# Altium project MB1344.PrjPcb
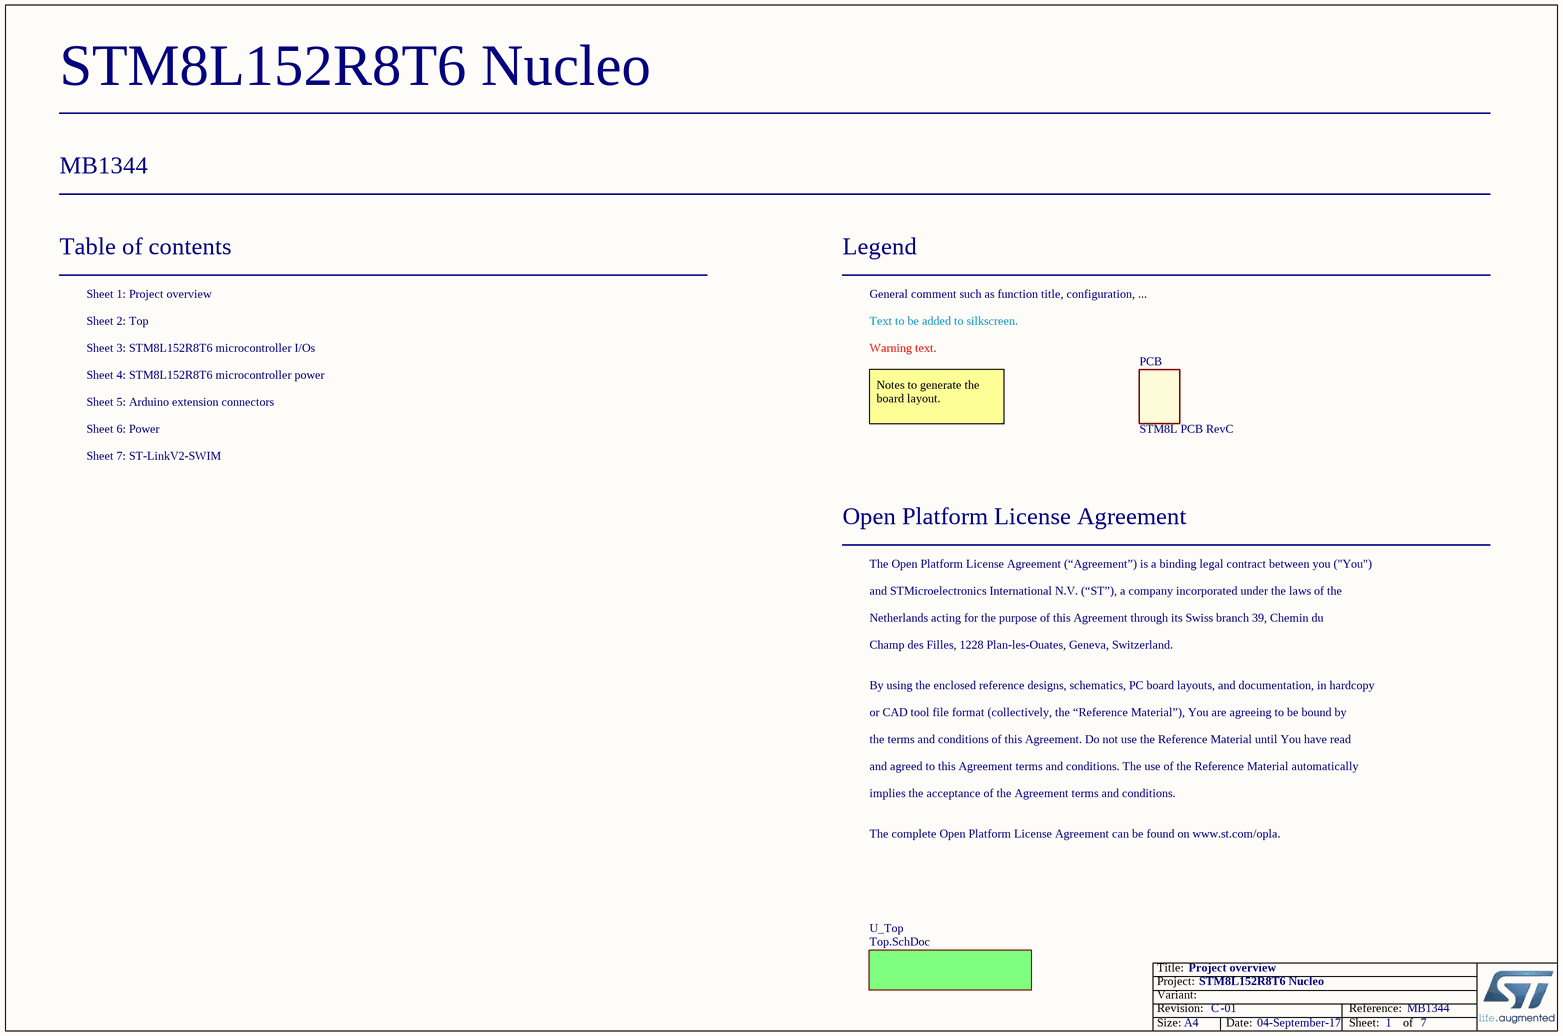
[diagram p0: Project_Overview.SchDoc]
Board_Reference: MB1344; Board_PCB_Revision: C; Board_Name: STM8L152R8T6 Nucleo; Board_Document_Date: 04-September-17; Board_Assembly_Revision: 01
7 sheets, 133 parts. Net scope: flat (ports and power ports of the same name join across sheets).
Board file: MB1344.PcbDoc
Sheets:
  Project_Overview.SchDoc
    U_Top = Top.SchDoc
      U_Power = Power.SchDoc
      U_ST-LinkV2_SWIM = ST-LinkV2_SWIM.SchDoc
      U_Arduino_extension_connectors = Arduino_extension_connectors.SchDoc
      U_STM8L152R8T6 microcontroller IOs = STM8L152R8T6 microcontroller IOs.SchDoc
      U_STM8L152R8T6 microcontroller power = STM8L152R8T6 microcontroller power.SchDoc

## Sheet Project_Overview.SchDoc: Project overview
size A4; ApprovedBy: Not used; CheckedBy: Not used; Author: Not used; CompanyName: STMicroelectronics; DrawnBy: Not used; Engineer: Not used; Organization: Not used; Address1: Not used; Address2: Not used; Address3: Not used; Address4: Not used; DocumentNumber: MB1134; Revision: Not used; SheetNumber: 1; SheetTotal: 7

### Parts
PCB  value STM8L PCB RevC  (hidden comment: PCB)

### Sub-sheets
U_Top = Top.SchDoc: no entries

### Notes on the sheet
- Table of contents
- Sheet 1: Project overview
- Legend
- General comment such as function title, configuration, ...
- Sheet 2: Top
- Sheet 3: STM8L152R8T6 microcontroller I/Os
- Sheet 4: STM8L152R8T6 microcontroller power
- Text to be added to silkscreen.
- Warning text.
- Sheet 6: Power
- Sheet 5: Arduino extension connectors
- Notes to generate the board layout.
- Sheet 7: ST-LinkV2-SWIM
- Open Platform License Agreement
- The Open Platform License Agreement (“Agreement”) is a binding legal contract between you ("You")
- and STMicroelectronics International N.V. (“ST”), a company incorporated under the laws of the
- Netherlands acting for the purpose of this Agreement through its Swiss branch 39, Chemin du
- Champ des Filles, 1228 Plan-les-Ouates, Geneva, Switzerland.
- By using the enclosed reference designs, schematics, PC board layouts, and documentation, in hardcopy
- or CAD tool file format (collectively, the “Reference Material”), You are agreeing to be bound by
- the terms and conditions of this Agreement. Do not use the Reference Material until You have read
- and agreed to this Agreement terms and conditions. The use of the Reference Material automatically
- implies the acceptance of the Agreement terms and conditions.
- The complete Open Platform License Agreement can be found on www.st.com/opla.

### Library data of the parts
PCB = 1001001000655: 2-LAYE PCB,White Soldermask,Blue ink PANTONE 2955 Silkscreen,lead Gold,70mm*82.5mm,STM8L PCB RevC; Manufacturer: XJX

## Sheet Top.SchDoc: Top
size A4; Date: Not used; ApprovedBy: Not used; CheckedBy: Not used; Author: Not used; CompanyName: STMicroelectronics; DrawnBy: Not used; Engineer: Not used; Organization: Not used; Address1: Not used; Address2: Not used; Address3: Not used; Address4: Not used; DocumentNumber: MB1134; Revision: Not used; SheetNumber: 2; SheetTotal: 7
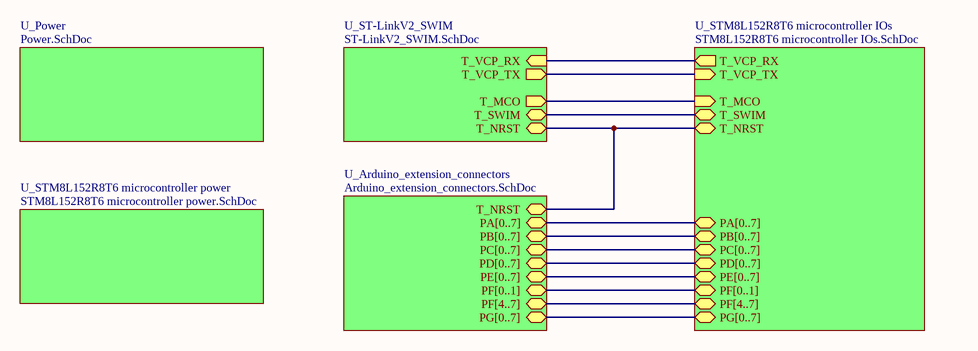
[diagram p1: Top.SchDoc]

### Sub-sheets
U_Arduino_extension_connectors = Arduino_extension_connectors.SchDoc: PA[0..7] (bidir), PB[0..7] (bidir), PC[0..7] (bidir), PD[0..7] (bidir), PE[0..7] (bidir), PF[0..1] (bidir), PF[4..7] (bidir), PG[0..7] (bidir), T_NRST (bidir)
U_Power = Power.SchDoc: no entries
U_ST-LinkV2_SWIM = ST-LinkV2_SWIM.SchDoc: T_VCP_RX (in), T_VCP_TX (out), T_MCO (out), T_NRST (bidir), T_SWIM (bidir)
U_STM8L152R8T6 microcontroller IOs = STM8L152R8T6 microcontroller IOs.SchDoc: T_VCP_TX (in), T_VCP_RX (out), T_NRST (bidir), T_SWIM (bidir), T_MCO (in), PA[0..7] (bidir), PB[0..7] (bidir), PC[0..7] (bidir), PD[0..7] (bidir), PE[0..7] (bidir), PF[0..1] (bidir), PF[4..7] (bidir), PG[0..7] (bidir)
U_STM8L152R8T6 microcontroller power = STM8L152R8T6 microcontroller power.SchDoc: no entries

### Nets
(unnamed): sheet U_ST-LinkV2_SWIM/T_VCP_RX, sheet U_STM8L152R8T6 microcontroller IOs/T_VCP_RX
(unnamed): sheet U_ST-LinkV2_SWIM/T_VCP_TX, sheet U_STM8L152R8T6 microcontroller IOs/T_VCP_TX  [a separate net that carries the same name]
(unnamed): sheet U_ST-LinkV2_SWIM/T_MCO, sheet U_STM8L152R8T6 microcontroller IOs/T_MCO  [a separate net that carries the same name]
(unnamed): sheet U_ST-LinkV2_SWIM/T_NRST, sheet U_Arduino_extension_connectors/T_NRST, sheet U_STM8L152R8T6 microcontroller IOs/T_NRST  [a separate net that carries the same name]
(unnamed): sheet U_ST-LinkV2_SWIM/T_SWIM, sheet U_STM8L152R8T6 microcontroller IOs/T_SWIM  [a separate net that carries the same name]

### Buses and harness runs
bus sheet U_Arduino_extension_connectors/PA[0..7] = sheet U_STM8L152R8T6 microcontroller IOs/PA[0..7]
bus sheet U_Arduino_extension_connectors/PB[0..7] = sheet U_STM8L152R8T6 microcontroller IOs/PB[0..7]
bus sheet U_Arduino_extension_connectors/PC[0..7] = sheet U_STM8L152R8T6 microcontroller IOs/PC[0..7]
bus sheet U_Arduino_extension_connectors/PD[0..7] = sheet U_STM8L152R8T6 microcontroller IOs/PD[0..7]
bus sheet U_Arduino_extension_connectors/PE[0..7] = sheet U_STM8L152R8T6 microcontroller IOs/PE[0..7]
bus sheet U_Arduino_extension_connectors/PF[0..1] = sheet U_STM8L152R8T6 microcontroller IOs/PF[0..1]
bus sheet U_Arduino_extension_connectors/PF[4..7] = sheet U_STM8L152R8T6 microcontroller IOs/PF[4..7]
bus sheet U_Arduino_extension_connectors/PG[0..7] = sheet U_STM8L152R8T6 microcontroller IOs/PG[0..7]

## Sheet Power.SchDoc: Power
size A4; Date: Not used; ApprovedBy: Not used; CheckedBy: Not used; Author: Not used; CompanyName: STMicroelectronics; DrawnBy: Not used; Engineer: Not used; Organization: Not used; Address1: Not used; Address2: Not used; Address3: Not used; Address4: Not used; DocumentNumber: MB1134; Revision: Not used; SheetNumber: 6; SheetTotal: 7
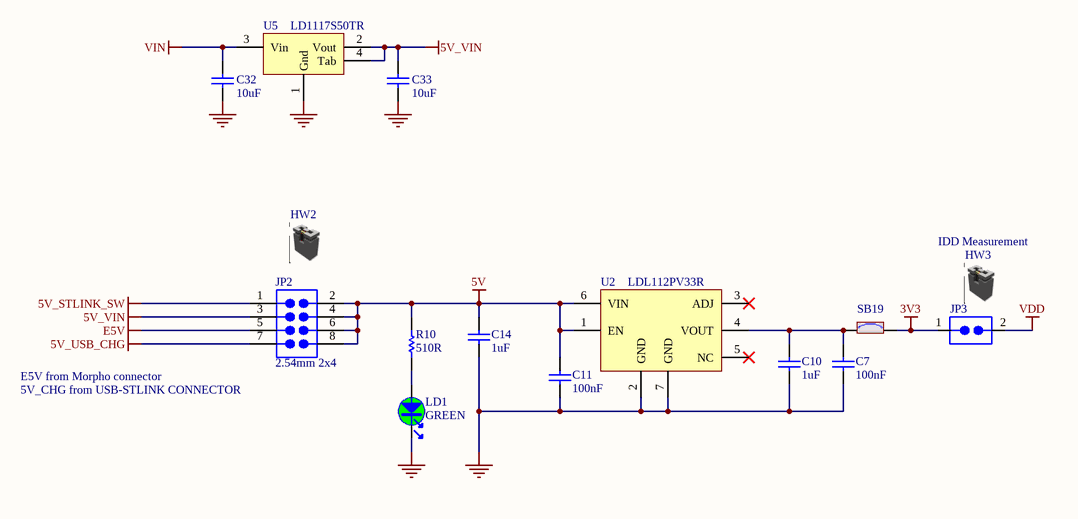
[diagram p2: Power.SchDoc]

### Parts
C7  value 100nF  [C0603]  (hidden comment: C)
C10  value 1uF  [C0603]  (hidden comment: C)
C11  value 100nF  [C0603]  (hidden comment: C)
C14  value 1uF  [C0603]  (hidden comment: C)
C32  value 10uF  [C0805]  (hidden comment: C)
C33  value 10uF  [C0805]  (hidden comment: C)
HW2  Shunt  (value not drawn)  (mechanical)
HW3  Shunt  (value not drawn)  (mechanical)
JP2  value 2.54mm 2x4  [HDRVS8W64P254_2X4_1016X750X850P]  (hidden comment: HEAD2X4)
JP3  SIP2  [HDRV2W64P254_1X2_508X254X854P]  (value not drawn)
LD1  value GREEN  [D0603]  (hidden comment: LED_green)
R10  value 510R  [R0603]  (hidden comment: R)
SB19  SB_ON  [JP2_SMD]  (value not drawn)
U2  LDL112PV33R  [DFN300X300X80-7N]
U5  LD1117S50TR  [SOT-223]

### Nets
3V3: JP3.1 SB19.2
5V: C11.2 C14.2 JP2.2 JP2.4 JP2.6 JP2.8 R10.2 U2.1(EN) U2.6(VIN)
5V_STLINK_SW: JP2.1
5V_USB_CHG: JP2.7
5V_VIN: C33.2 JP2.3 U5.2(Vout) U5.4(Tab)
E5V: JP2.5
GND: C7.1 C10.1 C11.1 C14.1 C32.1 C33.1 LD1.1 U2.2(GND) U2.7(GND) U5.1(Gnd)
VDD: JP3.2
VIN: C32.2 U5.3(Vin)
NetC7_2: C7.2 C10.2 SB19.1 U2.4(VOUT)
NetLD1_2: LD1.2 R10.1

Not connected (* = marked no-connect by the designer): U2 3(ADJ)* 5(NC)*

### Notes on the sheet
- (near HW3) IDD Measurement
- E5V from Morpho connector
- 5V_CHG from USB-STLINK CONNECTOR

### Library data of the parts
C7 C11 = 1004001100110: CAP,100NF,+/-10%,X7R,50V,SMD0603; Manufacturer: MURATA; Manufacturer_Part_Number: GRM188R71H104KA93D
C10 C14 = 1004001100120: CAP,1UF,+/-10%,X7R,16V,SMD0603; Manufacturer: MURATA; Manufacturer_Part_Number: GRM188R71C105KA12D
C32 C33 = 1004001100159: CAP,10UF,+/-10%,X5R,16V,SMD0805; Manufacturer: MURATA; Manufacturer_Part_Number: GRM21BR61C106KE15L
HW2 = 1009016000005: Connector,Shunt,open type 2Pin,2.54MM Pitch,6MM Height,Gold Flash 1u,black,Bulk; Manufacturer: TOWNES; Manufacturer_Part_Number: MJ501-EOGF-B-K
HW3 = 1009016000005: Connector,Shunt,open type 2Pin,2.54MM Pitch,6MM Height,Gold Flash 1u,black,Bulk; Manufacturer_Part_Number: MJ501-EOGF-B-K; Manufacturer: TOWNES
JP2 = 1009001100223: Connector,Pin Header,Straight,Male,2x4Pin,2.54MM pitch,6.0mm,Gold Flash  Over NI,black,SMD; Manufacturer: MTCONN; Manufacturer_Part_Number: PD254NV-08GC310
JP3 = 1009001200085R1: Connector,Pin Header,Straight,Male,1x2Pin,2.54MM pitch,6.0,3.0,Au over 50 u nickle , black,DIP; Manufacturer: MTCONN; Manufacturer_Part_Number: JT254-D180-102-001; Value: 2.54mm 1x2
LD1 = 1006001100094: LED,Yellow-Green,Water clear,20mA,0603,573nm,Vf:2.0v;; Manufacturer: EVERLIGHT; Manufacturer_Part_Number: 19-213SYGC/S530-E2/TR8
R10 = 1003001100424: RES,510R,+/-5%,1/10W,SMD0603; Manufacturer: YAGEO; Manufacturer_Part_Number: RC0603JR-07510RL
SB19 = PN029: RES,0R,+/-5%,1/10W,SMD0603; Manufacturer: YAGEO; Manufacturer_Part_Number: RC0603JR-070RL
U2 = 1002006100237C: IC,LDO,1.2 A low quiescent current LDO with reverse current protection 3.3V,LDL112PV33R,DFN3x3,SMD; Manufacturer: ST
U5 = 1002006100169C: IC,LDO,5V,LD1117S50TR,SOT223,STMicroelectronics,9176133; Manufacturer: ST

## Sheet ST-LinkV2_SWIM.SchDoc: ST-Link/V2 SWIM mode
size A4; Date: Not used; ApprovedBy: Not used; CheckedBy: Not used; Author: Not used; CompanyName: STMicroelectronics; DrawnBy: Not used; Engineer: Not used; Organization: Not used; Address1: Not used; Address2: Not used; Address3: Not used; Address4: Not used; DocumentNumber: MB1134; Revision: Not used; SheetNumber: 7; SheetTotal: 7
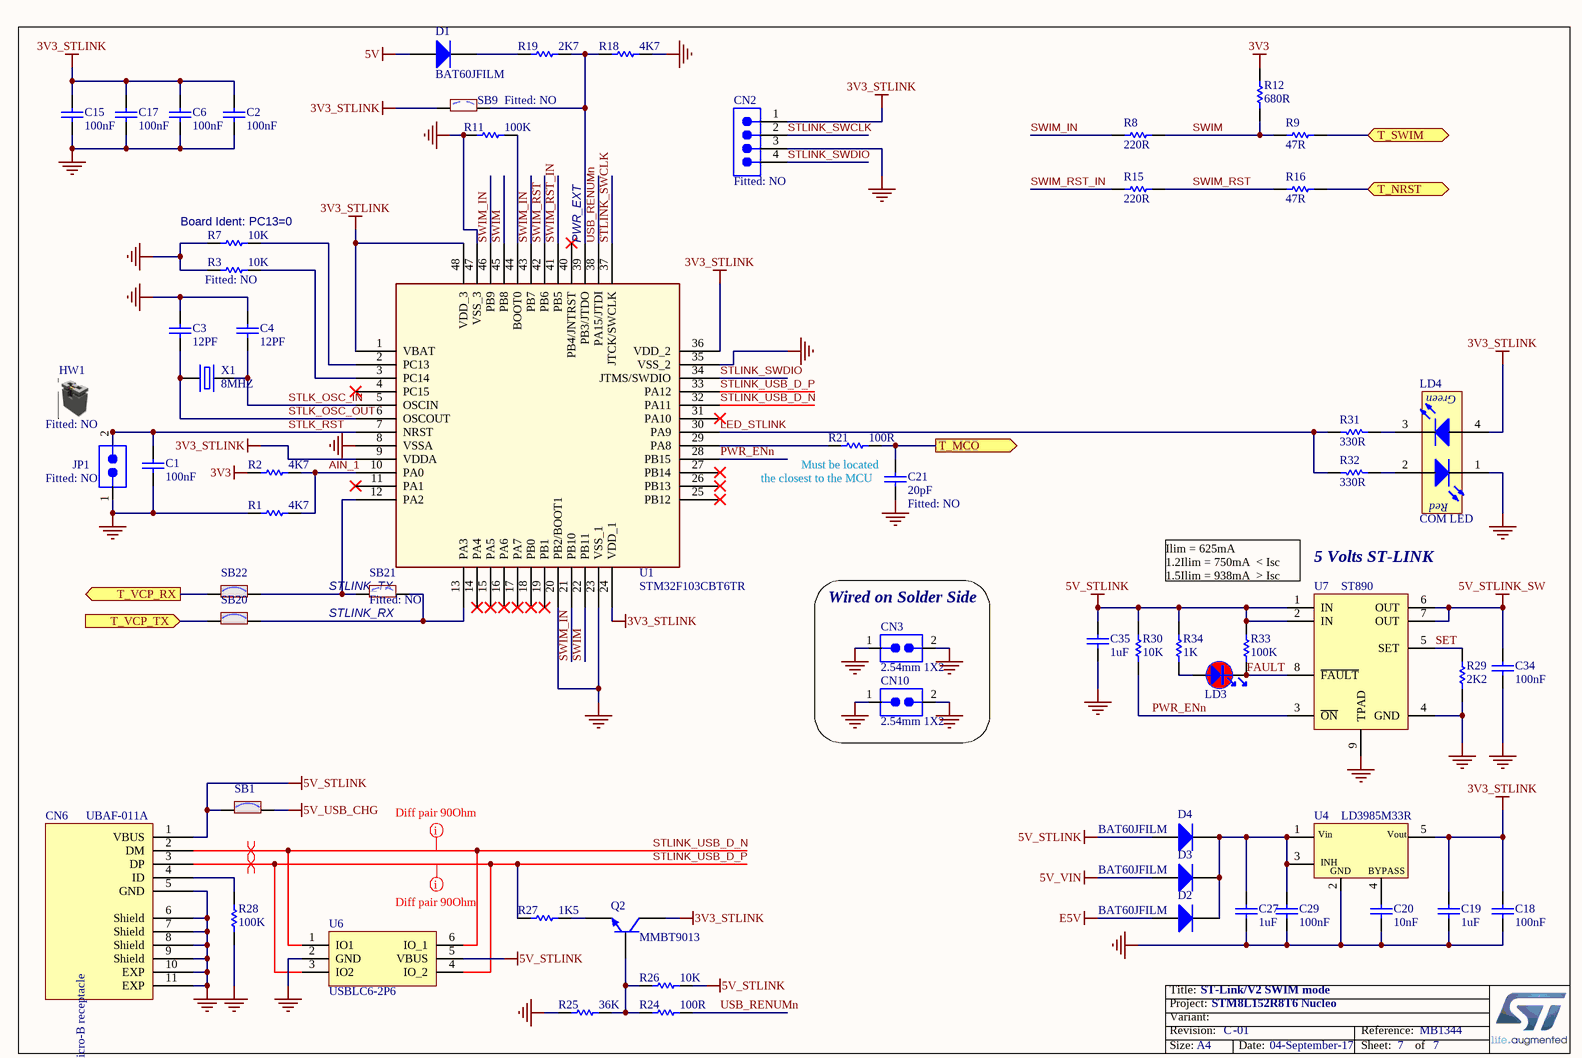
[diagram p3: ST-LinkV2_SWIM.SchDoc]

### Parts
C1  value 100nF  [C0603]  (hidden comment: C)
C2  value 100nF  [C0603]  (hidden comment: C)
C3  value 12PF  [C0603]  (hidden comment: C)
C4  value 12PF  [C0603]  (hidden comment: C)
C6  value 100nF  [C0603]  (hidden comment: C)
C15  value 100nF  [C0603]  (hidden comment: C)
C17  value 100nF  [C0603]  (hidden comment: C)
C18  value 100nF  [C0603]  (hidden comment: C)
C19  value 1uF  [C0603]  (hidden comment: C)
C20  value 10nF  [C0603]  (hidden comment: C)
C21  value 20pF  Fitted: NO  [C0603]  (hidden comment: C)
C27  value 1uF  [C0603]  (hidden comment: C)
C29  value 100nF  [C0603]  (hidden comment: C)
C34  value 100nF  [C0603]  (hidden comment: C)
C35  value 1uF  [C0603]  (hidden comment: C)
CN2  Fitted: NO  [HDRV4W64P254_1X4_1016X254X854P]  (hidden comment: SIP4)
CN3  value 2.54mm 1X2  [HDRV2W64P254_1X2_508X250X854P]  (hidden comment: SIP2)
CN6  value UBAF-011A  [USB-MICRO-B-5P-SMD_800X560]  (hidden comment: MICROUSB5_6)
CN10  value 2.54mm 1X2  [HDRV2W64P254_1X2_508X250X854P]  (hidden comment: SIP2)
D1  value BAT60JFILM  [SOD323]  (hidden comment: D)
D2  value BAT60JFILM  [SOD323]  (hidden comment: D)
D3  value BAT60JFILM  [SOD323]  (hidden comment: D)
D4  value BAT60JFILM  [SOD323]  (hidden comment: D)
HW1  Fitted: NO  (hidden comment: Shunt)  (mechanical)
JP1  Fitted: NO  [HDRV2W64P254_1X2_508X254X854P]  (hidden comment: SIP2)
LD3  LED_red  [D0603]  (value not drawn)
LD4  value COM LED  [PLCC150P350X280X210-4N]  (hidden comment: LED4_RED/GRN)
Q2  value MMBT9013  [TO-236]  (hidden comment: NPN)
R1  value 4K7  [R0603]  (hidden comment: R)
R2  value 4K7  [R0603]  (hidden comment: R)
R3  value 10K  Fitted: NO  [R0603]  (hidden comment: R)
R7  value 10K  [R0603]  (hidden comment: R)
R8  value 220R  [R0603]  (hidden comment: R)
R9  value 47R  [R0603]  (hidden comment: R)
R11  value 100K  [R0603]  (hidden comment: R)
R12  value 680R  [R0603]  (hidden comment: R)
R15  value 220R  [R0603]  (hidden comment: R)
R16  value 47R  [R0603]  (hidden comment: R)
R18  value 4K7  [R0603]  (hidden comment: R)
R19  value 2K7  [R0603]  (hidden comment: R)
R21  value 100R  [R0603]  (hidden comment: R)
R24  value 100R  [R0603]  (hidden comment: R)
R25  value 36K  [R0603]  (hidden comment: R)
R26  value 10K  [R0603]  (hidden comment: R)
R27  value 1K5  [R0603]  (hidden comment: R)
R28  value 100K  [R0603]  (hidden comment: R)
R29  value 2K2  [R0603]  (hidden comment: R)
R30  value 10K  [R0603]  (hidden comment: R)
R31  value 330R  [R0603]  (hidden comment: R)
R32  value 330R  [R0603]  (hidden comment: R)
R33  value 100K  [R0603]  (hidden comment: R)
R34  value 1K  [R0603]  (hidden comment: R)
SB1  SB_ON  [JP2_SMD]  (value not drawn)
SB9  Fitted: NO  [JP2_SMD]  (hidden comment: SB_OFF)
SB20  SB_ON  [JP2_SMD]  (value not drawn)
SB21  Fitted: NO  [JP2_SMD]  (hidden comment: SB_OFF)
SB22  SB_ON  [JP2_SMD]  (value not drawn)
U1  value STM32F103CBT6TR  [QFP50P900X900X160-48N]  (hidden comment: STM32F103CBT6)
U4  LD3985M33R  [SOT23-5]
U6  USBLC6-2P6  [SOT-666]
U7  ST890  [SOIC127P600X175-8N+PQFN65P300X300X90_HS-9N]
X1  value 8MHZ  [XTAL320X250X100N]  (hidden comment: X)

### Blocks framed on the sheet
Wired on Solder Side: CN3 CN10

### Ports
T_MCO (out), T_NRST (bidir), T_SWIM (bidir), T_VCP_RX (out), T_VCP_TX (in)

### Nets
3V3: R2.1 R12.2
3V3_STLINK: C2.2 C6.2 C15.2 C17.2 C18.2 C19.2 CN2.1 LD4.4(YellowGreen_anode) Q2.3(C) SB9.1 U1.1(VBAT) U1.9(VDDA) U1.24(VDD_1) U1.36(VDD_2) U1.48(VDD_3) U4.5(Vout)
5V: D1.2
5V_STLINK: C35.1 CN6.1(VBUS) D4.2 R26.1 R30.1 R33.2 R34.2 SB1.1 U6.5(VBUS) U7.1(IN) U7.2(IN)
5V_STLINK_SW: C34.2 U7.6(OUT) U7.7(OUT)
5V_USB_CHG: SB1.2
5V_VIN: D3.2
E5V: D2.2
GND: C1.1 C2.1 C3.2 C4.2 C6.1 C15.1 C17.1 C18.1 C19.1 C20.1 C21.1 C27.1 C29.1 C34.1 C35.2 CN2.3 CN3.1 CN3.2 CN6.5(GND) CN6.6(Shield) CN6.7(Shield) CN6.8(Shield) CN6.9(Shield) CN6.10(EXP) CN6.11(EXP) CN10.1 CN10.2 JP1.1 LD4.1(RED_cathode) R1.1 R3.1 R7.1 R11.1 R18.2 R25.1 R28.1 R29.1 U1.8(VSSA) U1.20(PB2/BOOT1) U1.23(VSS_1) U1.35(VSS_2) U1.47(VSS_3) U4.2(GND) U6.2(GND) U7.4(GND) U7.9(TPAD)
AIN_1: R1.2 R2.2 U1.10(PA0)
FAULT: LD3.1 R33.1 U7.8(~{FAULT})
LED_STLINK: R31.2 R32.2 U1.30(PA9)
PWR_ENn: R30.2 U1.28(PB15) U7.3(~{ON})
SET: R29.2 U7.5(SET)
STLINK_SWCLK: CN2.2 U1.37(JTCK/SWCLK)
STLINK_SWDIO: CN2.4 U1.34(JTMS/SWDIO)
STLINK_USB_D_N: CN6.2(DM) U1.32(PA11) U6.1(IO1) U6.6(IO_1)
STLINK_USB_D_P: CN6.3(DP) R27.2 U1.33(PA12) U6.3(IO2) U6.4(IO_2)
STLK_OSC_IN: C4.1 U1.5(OSCIN) X1.2
STLK_OSC_OUT: C3.1 U1.6(OSCOUT) X1.1
STLK_RST: C1.2 JP1.2 U1.7(NRST)
SWIM: R8.1 R9.2 R12.1 U1.22(PB11) U1.45(PB8)
SWIM_IN: R8.2 U1.21(PB10) U1.43(PB7) U1.46(PB9)
SWIM_RST: R15.1 R16.2 U1.42(PB6)
SWIM_RST_IN: R15.2 U1.41(PB5)
T_MCO: C21.2 R21.2 ; port T_MCO
T_NRST: R16.1 ; port T_NRST
T_SWIM: R9.1 ; port T_SWIM
T_VCP_RX: SB22.1 ; port T_VCP_RX
T_VCP_TX: SB20.1 ; port T_VCP_TX
USB_RENUMn: R24.2 U1.38(PA15/JTDI)
NetC20_2: C20.2 U4.4(BYPASS)
NetC27_2: C27.2 C29.2 D2.1 D3.1 D4.1 U4.1(Vin) U4.3(CE)
NetCN6_4: CN6.4(ID) R28.2
NetD1_1: D1.1 R19.1
NetLD3_2: LD3.2 R34.1
NetLD4_2: LD4.2(Red_anode) R32.1
NetLD4_3: LD4.3(YellowGreen_cathode) R31.1
NetQ2_1: Q2.1(B) R24.1 R25.2 R26.2
NetQ2_2: Q2.2(E) R27.1
NetR3_2: R3.2 U1.3(PC14)
NetR7_2: R7.2 U1.2(PC13)
NetR11_2: R11.2 U1.44(BOOT0)
NetR18_1: R18.1 R19.2 SB9.2 U1.39(PB3/JTDO)
NetR21_1: R21.1 U1.29(PA8)
NetSB20_2: SB20.2 SB21.2 U1.13(PA3)
NetSB21_1: SB21.1 SB22.2 U1.12(PA2)

Not connected (* = marked no-connect by the designer): U1 4(PC15)* 11(PA1)* 14(PA4)* 15(PA5)* 16(PA6)* 17(PA7)* 18(PB0)* 19(PB1)* 25(PB12)* 26(PB13)* 27(PB14)* 31(PA10)* 40(PB4/JNTRST)*

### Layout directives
mark named Diff pair 90Ohm: STLINK_USB_D_N, STLINK_USB_D_P
differential pair: STLINK_USB_D_N, STLINK_USB_D_P

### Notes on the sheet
- (near R7) Board Ident: PC13=0
- (near U1) PWR_EXT
- (near C21) Must be located
- (near C21) the closest to the MCU
- STLINK_TX
- (near U7) Ilim = 625mA
  1.2Ilim = 750mA  < Isc
  1.5Ilim = 938mA  > Isc
- (near U7) 5 Volts ST-LINK
- STLINK_RX

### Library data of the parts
C1 C2 C6 C15 C17 C18 C29 C34 = 1004001100110: as C7 on sheet Power
C3 C4 = 1004001100897: CAP,12PF,+/-5%,NPO,50V,SMD0603; Manufacturer: Yageo; Manufacturer_Part_Number: CC0603JRNPO9BN120
C19 C27 C35 = 1004001100120: as C10 on sheet Power
C20 = 1004001100103: CAP,10NF,+/-10%,X7R,50V,SMD0603; Manufacturer: MURATA; Manufacturer_Part_Number: GRM188R71H103KA01D
C21 = 1004001100069: CAP,20PF,+/-5%,C0G,50V,SMD0603; Manufacturer: MURATA; Manufacturer_Part_Number: GRM1885C1H200JA01D
CN2 = 1009001200307: Connector,Pin Header,Straight,Male,1x4Pin,2.54MM pitch,6.0,3.0,Au over 50 u nickle , black,DIP; Manufacturer: MTCONN; Manufacturer_Part_Number: JT254-D180-104-001; Value: 2.54mm 1x4
CN3 CN10 = 1009001200378: Connector,Pin Header,Straight,Male,2.54MM pitch,1x2P,6.0mm,10mm,Au Over 50u"NI, black,DIP; Manufacturer: MTCONN; Manufacturer_Part_Number: JTP254-D180-102-185L
CN6 = 1009007100040R2: Connector,MicroUSB B port,5 Position,Right Angle,Gold Flash 1u, black,SMD; Manufacturer: MTCONN
D1-D4 = 1006002100076C: DIODE SCHOTTKY,BAT60JFILM,10V,3A, SOD323/A,ST,(X3 Code 9151097)
HW1 = 1009016000005: as HW2 on sheet Power
JP1 = 1009001200085R1: as JP3 on sheet Power
LD3 = 1006001100139: LED,Briliant Red,WATER CLEAR,0603 TR; Manufacturer: EVERLIGHT; Value: 19-213/R6C-AP1Q2B/3T
LD4 = 1006001100098: LED IND RED/GRN TOP MOUNT 4PLCC,3.2*2.8MM; Manufacturer: AVAGO; Manufacturer_Part_Number: HSMF-A201-A00J1
Q2 = 1006013100039: Trans,NPN,MMBT9013G-I-AE3-R,Ic:500mA,Vceo:20v, SOT-23,SMD; Manufacturer: UTC
R1 R2 R18 = 1003001100221: RES,4K7,+/-5%,1/10W,SMD0603; Manufacturer: YAGEO; Manufacturer_Part_Number: RC0603JR-074K7L
R3 R7 R26 R30 = 1003001100235: RES,10K,+/-5%,1/10W,SMD0603; Manufacturer: YAGEO; Manufacturer_Part_Number: RC0603JR-0710KL
R8 R15 = 1003001100192: RES,220R,+/-5%,1/10W,SMD0603; Manufacturer: YAGEO; Manufacturer_Part_Number: RC0603JR-07220RL
R9 R16 = 1003001100178: RES,47R,+/-5%,1/10W,SMD0603; Manufacturer: YAGEO; Manufacturer_Part_Number: RC0603JR-0747RL
R11 R28 R33 = 1003001100269: RES,100K,+/-5%,1/10W,SMD0603; Manufacturer: YAGEO; Manufacturer_Part_Number: RC0603JR-07100KL
R12 = 1003001100200: RES,680R,+/-5%,1/10W,SMD0603; Manufacturer: YAGEO; Manufacturer_Part_Number: RC0603JR-07680RL
R19 = 1003001100467: RES,2K7,+/-1%,1/10W,SMD0603; Manufacturer: YAGEO; Manufacturer_Part_Number: RC0603FR-072K7L
R21 R24 = 1003001100186: RES,100R,+/-5%,1/10W,SMD0603; Manufacturer: YAGEO; Manufacturer_Part_Number: RC0603JR-07100RL
R25 = 1003001100368: RES,36K, +/-1%,1/10W,SMD0603; Manufacturer: YAGEO; Manufacturer_Part_Number: RC0603FR-0736KL
R27 = 1003001100207: RES,1K5,+/-5%,1/10W,SMD0603; Manufacturer: YAGEO; Manufacturer_Part_Number: RC0603JR-071K5L
R29 = 1003001100211: RES,2K2,+/-1%,1/10W,SMD0603; Manufacturer: YAGEO; Manufacturer_Part_Number: RC0603FR-072K2L
R31 R32 = 1003001100196: RES,330R,+/-5%,1/10W,SMD0603; Manufacturer: YAGEO; Manufacturer_Part_Number: RC0603JR-07330RL
R34 = 1003001100202: RES,1K,+/-5%,1/10W,SMD0603; Manufacturer: YAGEO; Manufacturer_Part_Number: RC0603JR-071KL
SB1 SB20 SB22 = PN029: as SB19 on sheet Power
SB9 SB21 = PN034: RES,0R,+/-5%,1/10W,SMD0603; Manufacturer: YAGEO; Manufacturer_Part_Number: RC0603JR-070RL
U1 = 1002001100035C: IC, ARM Cortex-M3 MCU,STM32F103CBT6,LQFP-48,SMD,TR,(9175111),customer supply; Manufacturer: ST
U4 = 1002006100166C: IC,LDO,3.3V,LD3985M33R,SOT23-5L,ST,(X3 Code 9176161)
U6 = 1002020100274C: IC,ESD Protection for High Speed Interface Protection 2.5 PF Low Cap,USBLC6-2P6, SOT-666,SMD,TR; Manufacturer: ST
U7 = 1002004100103C: IC PWR SWITCH,ST890CDR,SO-8,ST,(X3 Code 9172002)
X1 = 1008002100145C: CRYSTAL, 8pF, -+50PPM,NX3225GD-8MHz-EXS00A-CG04874,SMT; Manufacturer: NDK

## Sheet Arduino_extension_connectors.SchDoc: Arduino extension connectors
size A4; Date: Not used; ApprovedBy: Not used; CheckedBy: Not used; Author: Not used; CompanyName: STMicroelectronics; DrawnBy: Not used; Engineer: Not used; Organization: Not used; Address1: Not used; Address2: Not used; Address3: Not used; Address4: Not used; DocumentNumber: MB1134; Revision: Not used; SheetNumber: 5; SheetTotal: 7
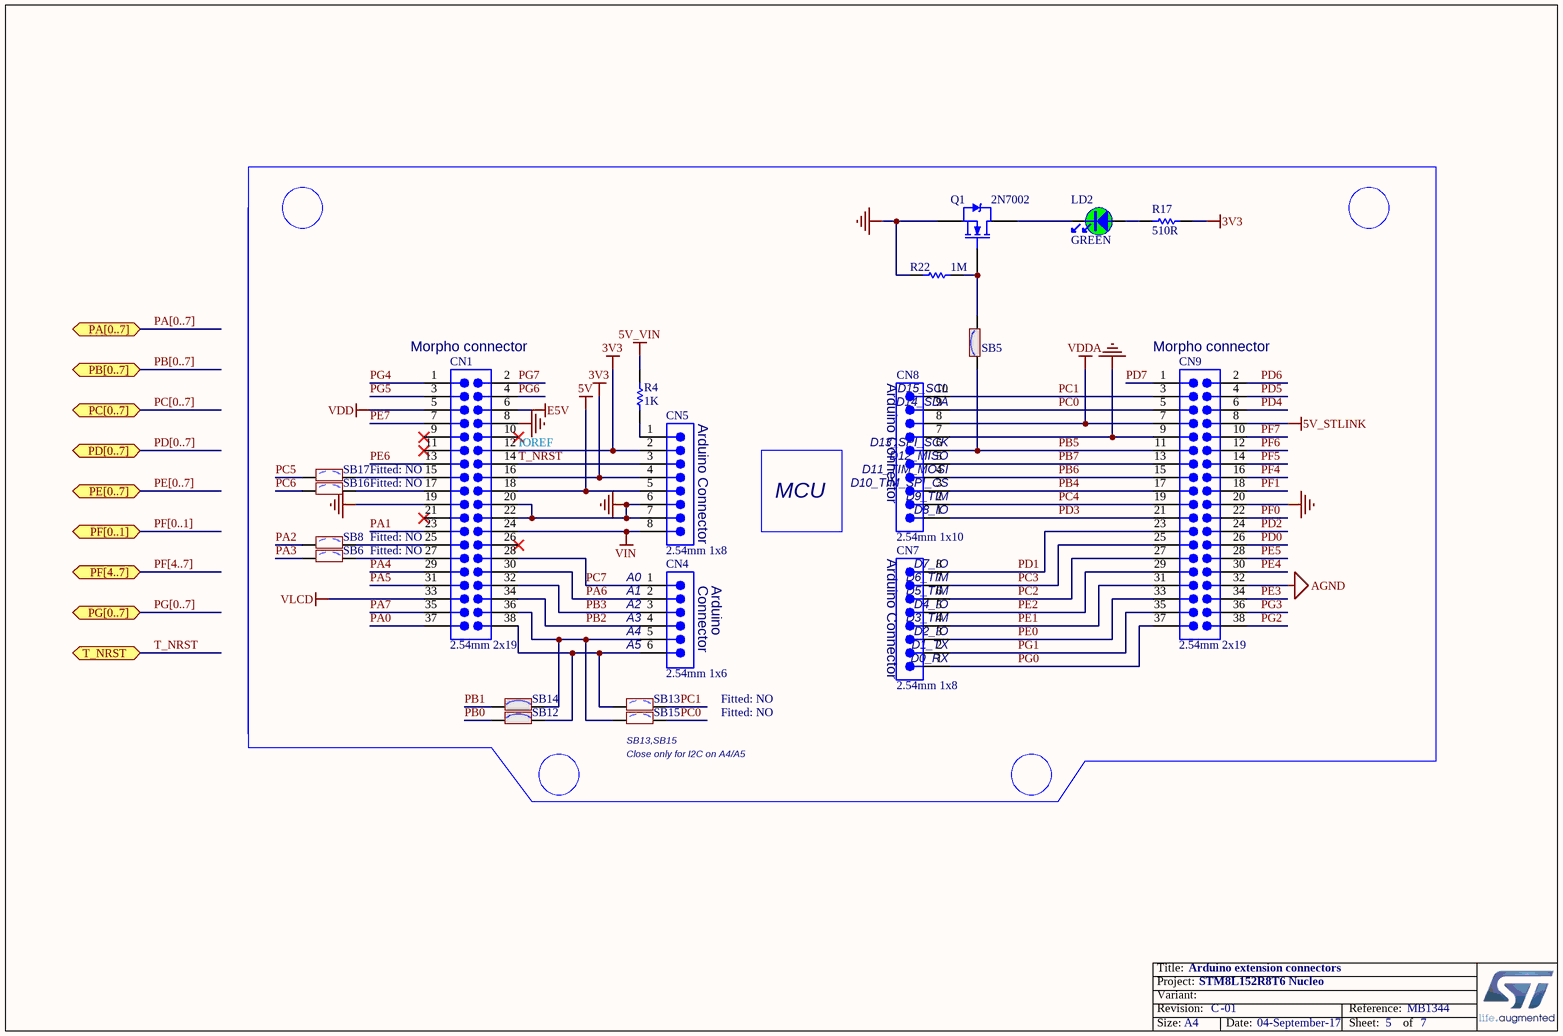
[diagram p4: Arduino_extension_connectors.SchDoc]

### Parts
CN1  value 2.54mm 2x19  [HDRV38W64P254_2X19_4826X508X838P]  (hidden comment: HEAD2X19)
CN4  value 2.54mm 1x6  [SOKV2W64P254_1X6_1574X250X850P]  (hidden comment: SIP6)
CN5  value 2.54mm 1x8  [SOKV2W64P254_1X8_2082X250X850P]  (hidden comment: SIP8)
CN7  value 2.54mm 1x8  [SOKV2W64P254_1X8_2082X250X850P]  (hidden comment: SIP8)
CN8  value 2.54mm 1x10  [SOKV2W64P254_1X10_2590X250X850P]  (hidden comment: SIP10)
CN9  value 2.54mm 2x19  [HDRV38W64P254_2X19_4826X508X838P]  (hidden comment: HEAD2X19)
LD2  value GREEN  [D0603]  (hidden comment: LED_green)
Q1  value 2N7002  [TO-236]  (hidden comment: NMOS)
R4  value 1K  [R0603]  (hidden comment: R)
R17  value 510R  [R0603]  (hidden comment: R)
R22  value 1M  [R0603]  (hidden comment: R)
SB5  SB_ON  [JP2_SMD]  (value not drawn)
SB6  Fitted: NO  [JP2_SMD]  (hidden comment: SB_OFF)
SB8  Fitted: NO  [JP2_SMD]  (hidden comment: SB_OFF)
SB12  SB_ON  [JP2_SMD]  (value not drawn)
SB13  Fitted: NO  [JP2_SMD]  (hidden comment: SB_OFF)
SB14  SB_ON  [JP2_SMD]  (value not drawn)
SB15  Fitted: NO  [JP2_SMD]  (hidden comment: SB_OFF)
SB16  Fitted: NO  [JP2_SMD]  (hidden comment: SB_OFF)
SB17  Fitted: NO  [JP2_SMD]  (hidden comment: SB_OFF)

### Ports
PA[0..7] (bidir), PB[0..7] (bidir), PC[0..7] (bidir), PD[0..7] (bidir), PE[0..7] (bidir), PF[0..1] (bidir), PF[4..7] (bidir), PG[0..7] (bidir), T_NRST

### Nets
3V3: CN1.12 CN1.16 CN5.2 CN5.4 R17.1
5V: CN1.18 CN5.5
5V_STLINK: CN9.8
5V_VIN: R4.2
AGND: CN9.32
E5V: CN1.6
GND: CN1.8 CN1.19 CN1.20 CN1.22 CN5.6 CN5.7 CN8.7 CN9.9 CN9.20 Q1.2(S) R22.1
VDD: CN1.5
VDDA: CN8.8 CN9.7
VIN: CN1.24 CN5.8
VLCD: CN1.33
PA0: CN1.37
PA1: CN1.23
PA2: SB8.1
PA3: SB6.1
PA4: CN1.29
PA5: CN1.31
PA6: CN1.30 CN4.2
PA7: CN1.35
PB0: SB12.1
PB1: SB14.1
PB2: CN1.34 CN4.4
PB3: CN1.32 CN4.3
PB4: CN8.3 CN9.17
PB5: CN8.6 CN9.11 SB5.1
PB6: CN8.4 CN9.15
PB7: CN8.5 CN9.13
PC0: CN8.9 CN9.5 SB15.2
PC1: CN8.10 CN9.3 SB13.2
PC2: CN7.6 CN9.27
PC3: CN7.7 CN9.25
PC4: CN8.2 CN9.19
PC5: SB17.1
PC6: SB16.1
PC7: CN1.28 CN4.1
PD0: CN9.26
PD1: CN7.8 CN9.23
PD2: CN9.24
PD3: CN8.1 CN9.21
PD4: CN9.6
PD5: CN9.4
PD6: CN9.2
PD7: CN9.1
PE0: CN7.3 CN9.33
PE1: CN7.4 CN9.31
PE2: CN7.5 CN9.29
PE3: CN9.34
PE4: CN9.30
PE5: CN9.28
PE6: CN1.13
PE7: CN1.7
PF0: CN9.22
PF1: CN9.18
PF4: CN9.16
PF5: CN9.14
PF6: CN9.12
PF7: CN9.10
PG0: CN7.1 CN9.37
PG1: CN7.2 CN9.35
PG2: CN9.38
PG3: CN9.36
PG4: CN1.1
PG5: CN1.3
PG6: CN1.4
PG7: CN1.2
T_NRST: CN1.14 CN5.3 ; port T_NRST
NetCN1_15: CN1.15 SB17.2
NetCN1_17: CN1.17 SB16.2
NetCN1_25: CN1.25 SB8.2
NetCN1_27: CN1.27 SB6.2
NetCN1_36: CN1.36 CN4.5 SB14.2 SB15.1
NetCN1_38: CN1.38 CN4.6 SB12.2 SB13.1
NetCN5_1: CN5.1 R4.1
NetLD2_1: LD2.1 Q1.3(D)
NetLD2_2: LD2.2 R17.2
NetQ1_1: Q1.1(G) R22.2 SB5.2

Not connected (* = marked no-connect by the designer): CN1 9* 10* 11* 21* 26*

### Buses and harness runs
bus PA[0..7] = port PA[0..7]
bus PB[0..7] = port PB[0..7]
bus PC[0..7] = port PC[0..7]
bus PD[0..7] = port PD[0..7]
bus PE[0..7] = port PE[0..7]
bus PF[0..1] = port PF[0..1]
bus PF[4..7] = port PF[4..7]
bus PG[0..7] = port PG[0..7]

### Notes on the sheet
- (near CN1) Morpho connector
- (near CN8) Arduino Connector
- (near CN9) Morpho connector
- (near CN1) IOREF
- (near CN5) Arduino Connector
- D14_SDA
- D15_SCL
- (near CN8) D13_SPI_SCK
- MCU
- (near CN8) D8_IO
- (near CN8) D9_TIM
- (near CN8) D10_TIM_SPI_CS
- (near CN8) D12_MISO
- (near CN8) D11_TIM_MOSI
- (near CN4) A0
- (near CN4) Connector
- (near CN4) Arduino
- (near CN7) Arduino Connector
- (near CN7) D6_TIM
- (near CN7) D7_IO
- (near CN4) A1
- (near CN4) A2
- (near CN4) A3
- (near CN4) A4
- (near CN4) A5
- (near CN7) D1_TX
- (near CN7) D2_IO
- (near CN7) D4_IO
- (near CN7) D3_TIM
- (near CN7) D5_TIM
- (near CN7) D0_RX
- Close only for I2C on A4/A5
- (near SB15) SB13,SB15

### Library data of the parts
CN1 CN9 = 1009001200377: Connector,Pin Header,Straight,Male,2.54MM pitch,2x19P,6.0mm,10mm,Au Over 50u"NI, black,DIP; Manufacturer: MTCONN; Manufacturer_Part_Number: JTP254-D180-219-06L
CN4 = 1009002200189: Connector,Pin Socket,Straight,Female,1x6Pin,2.54MM pitch,8.5,9.92,Gold Flash 1u, black,DIP; Manufacturer: MTCONN; Manufacturer_Part_Number: JT254F-D180-850-106-10DO-G
CN5 CN7 = 1009002200162: Connector,Pin Socket,Straight,Female,1x8Pin,2.54MM pitch,8.5,9.92,Gold Flash 1u, black,DIP; Manufacturer: MTCONN; Manufacturer_Part_Number: JT254F-D180-850-108-10DO-G
CN8 = 1009002200163: Connector,Pin Socket,Straight,Female,1x10Pin,2.54MM pitch,8.5,9.92,Gold Flash 1u, black,DIP; Manufacturer: MTCONN; Manufacturer_Part_Number: JT254F-D180-850-110-10DO-G
LD2 = 1006001100094: as LD1 on sheet Power
Q1 = 1006015100003: Mosfet,N-Channel,2N7002,60V,115mA,SOT-23,SMD; Manufacturer: FAIRCHILD
R4 = 1003001100202: as R34 on sheet ST-LinkV2_SWIM
R17 = 1003001100424: as R10 on sheet Power
R22 = 1003001100291: RES,1M,+/-5%,1/10W,SMD0603; Manufacturer: YAGEO; Manufacturer_Part_Number: RC0603JR-071ML
SB5 SB12 SB14 = PN029: as SB19 on sheet Power
SB6 SB8 SB13 SB15-SB17 = PN034: as SB9 on sheet ST-LinkV2_SWIM

## Sheet STM8L152R8T6 microcontroller IOs.SchDoc: STM32 microcontroller I/Os
size A4; DocumentNumber: MB1134; Revision: C.3; SheetNumber: 3; SheetTotal: 7; Project: NUCLEO-XXXXRX
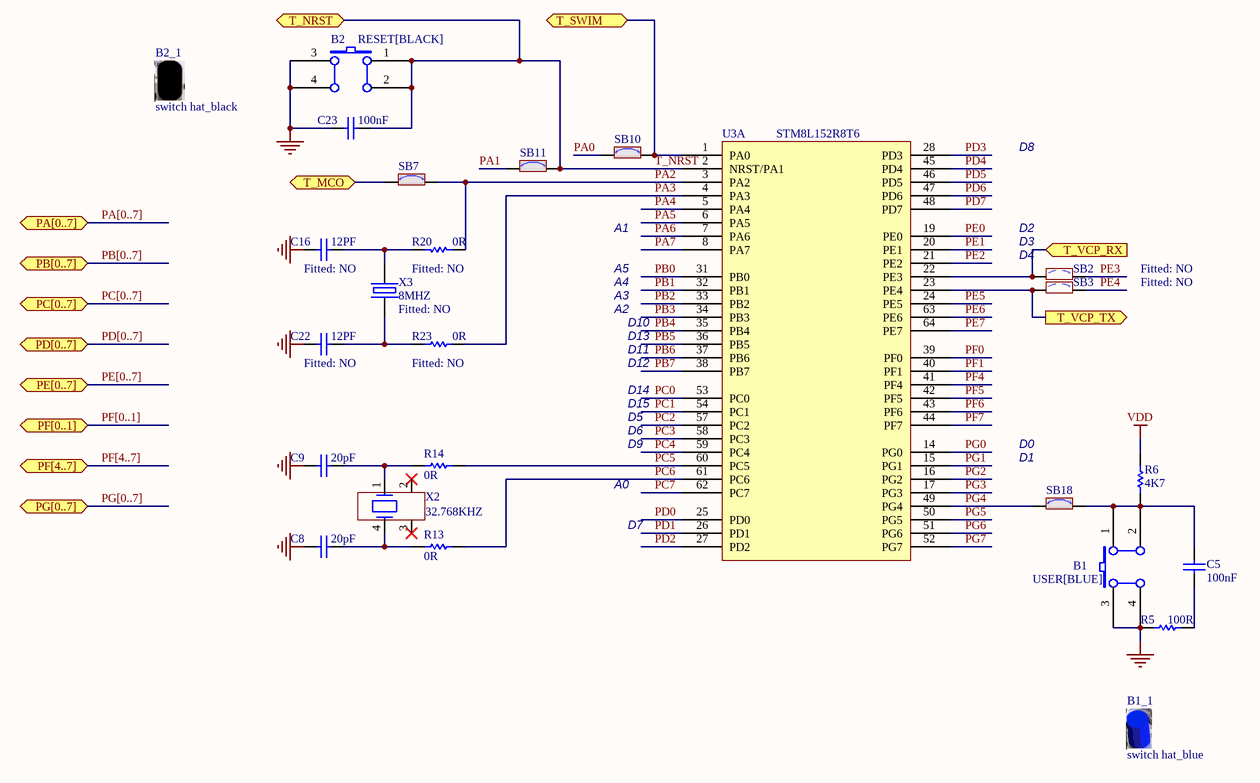
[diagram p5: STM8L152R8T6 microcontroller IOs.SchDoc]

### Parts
B1  value USER[BLUE]  [SW4P600X600]  (hidden comment: SW PUSHBUTTON)
B1_1  switch hat_blue  (mechanical)
B2  value RESET[BLACK]  [SW4P600X600]  (hidden comment: SW PUSHBUTTON)
B2_1  switch hat_black  (mechanical)
C5  value 100nF  [C0603]  (hidden comment: C)
C8  value 20pF  [C0603]  (hidden comment: C)
C9  value 20pF  [C0603]  (hidden comment: C)
C16  value 12PF  Fitted: NO  [C0603]  (hidden comment: C)
C22  value 12PF  Fitted: NO  [C0603]  (hidden comment: C)
C23  value 100nF  [C0603]  (hidden comment: C)
R5  value 100R  [R0603]  (hidden comment: R)
R6  value 4K7  [R0603]  (hidden comment: R)
R13  value 0R  [R0603]  (hidden comment: R)
R14  value 0R  [R0603]  (hidden comment: R)
R20  value 0R  Fitted: NO  [R0603]  (hidden comment: R)
R23  value 0R  Fitted: NO  [R0603]  (hidden comment: R)
SB2  Fitted: NO  [JP2_SMD]  (hidden comment: SB_OFF)
SB3  Fitted: NO  [JP2_SMD]  (hidden comment: SB_OFF)
SB7  SB_ON  [JP2_SMD]  (value not drawn)
SB10  SB_ON  [JP2_SMD]  (value not drawn)
SB11  SB_ON  [JP2_SMD]  (value not drawn)
SB18  SB_ON  [JP2_SMD]  (value not drawn)
U3  STM8L152R8T6  [QFP50P1000X1000X160-64N]  (part A of 2)
X2  value 32.768KHZ  [OSCCC380X800X250-4N]  (hidden comment: MC306)
X3  value 8MHZ  Fitted: NO  [XTAL320X250X100N]  (hidden comment: X)

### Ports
PA[0..7] (bidir), PB[0..7] (bidir), PC[0..7] (bidir), PD[0..7] (bidir), PE[0..7] (bidir), PF[0..1] (bidir), PF[4..7] (bidir), PG[0..7] (bidir), T_MCO, T_NRST, T_SWIM (bidir), T_VCP_RX (in), T_VCP_TX (out)

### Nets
GND: B1.3(B0) B1.4(B1) B2.3(B0) B2.4(B1) C8.1 C9.1 C16.1 C22.1 C23.1 R5.1
VDD: R6.2
PA0: SB10.1
PA1: SB11.1
PA2: R20.2 SB7.2 U3.3(PA2)
PA3: R23.1 U3.4(PA3)
PA4: U3.5(PA4)
PA5: U3.6(PA5)
PA6: U3.7(PA6)
PA7: U3.8(PA7)
PB0: U3.31(PB0)
PB1: U3.32(PB1)
PB2: U3.33(PB2)
PB3: U3.34(PB3)
PB4: U3.35(PB4)
PB5: U3.36(PB5)
PB6: U3.37(PB6)
PB7: U3.38(PB7)
PC0: U3.53(PC0)
PC1: U3.54(PC1)
PC2: U3.57(PC2)
PC3: U3.58(PC3)
PC4: U3.59(PC4)
PC5: R14.1 U3.60(PC5)
PC6: R13.1 U3.61(PC6)
PC7: U3.62(PC7)
PD0: U3.25(PD0)
PD1: U3.26(PD1)
PD2: U3.27(PD2)
PD3: U3.28(PD3)
PD4: U3.45(PD4)
PD5: U3.46(PD5)
PD6: U3.47(PD6)
PD7: U3.48(PD7)
PE0: U3.19(PE0)
PE1: U3.20(PE1)
PE2: U3.21(PE2)
PE3: SB2.2
PE4: SB3.2
PE5: U3.24(PE5)
PE6: U3.63(PE6)
PE7: U3.64(PE7)
PF0: U3.39(PF0)
PF1: U3.40(PF1)
PF4: U3.41(PF4)
PF5: U3.42(PF5)
PF6: U3.43(PF6)
PF7: U3.44(PF7)
PG0: U3.14(PG0)
PG1: U3.15(PG1)
PG2: U3.16(PG2)
PG3: U3.17(PG3)
PG4: SB18.1 U3.49(PG4)
PG5: U3.50(PG5)
PG6: U3.51(PG6)
PG7: U3.52(PG7)
T_MCO: SB7.1 ; port T_MCO
T_NRST: B2.1(A0) B2.2(A1) C23.2 SB11.2 U3.2(NRST/PA1) ; port T_NRST
T_SWIM: SB10.2 U3.1(PA0) ; port T_SWIM
T_VCP_RX: SB2.1 U3.22(PE3) ; port T_VCP_RX
T_VCP_TX: SB3.1 U3.23(PE4) ; port T_VCP_TX
NetB1_1: B1.1(A0) B1.2(A1) C5.2 R6.1 SB18.2
NetC5_1: C5.1 R5.2
NetC8_2: C8.2 R13.2 X2.4
NetC9_2: C9.2 R14.2 X2.1
NetC16_2: C16.2 R20.1 X3.2
NetC22_2: C22.2 R23.2 X3.1

Not connected (* = marked no-connect by the designer): X2 2* 3*

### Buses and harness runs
bus PA[0..7] = port PA[0..7]
bus PB[0..7] = port PB[0..7]
bus PC[0..7] = port PC[0..7]
bus PD[0..7] = port PD[0..7]
bus PE[0..7] = port PE[0..7]
bus PF[0..1] = port PF[0..1]
bus PF[4..7] = port PF[4..7]
bus PG[0..7] = port PG[0..7]

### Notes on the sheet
- D8
- A1
- D2
- D3
- A2
- A3
- A4
- A5
- D4
- D10
- D13
- D11
- D12
- D5
- D6
- D9
- D14
- D15
- D0
- A0
- (near SB18) D1
- D7

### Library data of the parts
B1 = 1010001100062: tact switch,blue,6*6,SMT,180,CTSM-644B-V-T/R,(TD-0341X-GO0）; Manufacturer: CHAU-HUA
B1_1 = 1010005000001: switch hat,blue,KTSC-62B; Manufacturer: CHAU-HUA
B2 = 1010001100063: tact switch,black,6*6,SMT,180,CTSM-644N-V-T/R,(TD-0341X-A00）; Manufacturer: CHAU-HUA
B2_1 = 1010005000002: switch hat,black,KTSC-62K; Manufacturer: CHAU-HUA
C5 C23 = 1004001100110: as C7 on sheet Power
C8 C9 = 1004001100069: as C21 on sheet ST-LinkV2_SWIM
C16 C22 = 1004001100897: as C3 on sheet ST-LinkV2_SWIM
R5 = 1003001100186: as R21 on sheet ST-LinkV2_SWIM
R6 = 1003001100221: as R1 on sheet ST-LinkV2_SWIM
R13 R14 R20 R23 = 1003001100161: RES,0R,+/-5%,1/10W,SMD0603; Manufacturer: YAGEO; Manufacturer_Part_Number: RC0603JR-070RL
SB2 SB3 = PN034: as SB9 on sheet ST-LinkV2_SWIM
SB7 SB10 SB11 SB18 = PN029: as SB19 on sheet Power
U3 = 1002002100257C: IC,MCU 8-bit 64KB FLASH 3.3V,STM8L152R8T6,LQFP64, SMD; Manufacturer: ST
X2 = 1008002100059: Crystal,ABS25-32.768KHZ-T,32.768KHz,+/-20PPM,12.5PF,8 x3.8MM,SMD; Manufacturer: Abracon
X3 = 1008002100145C: as X1 on sheet ST-LinkV2_SWIM

## Sheet STM8L152R8T6 microcontroller power.SchDoc: STM32 microcontroller power
size A4; DocumentNumber: MB1134; Revision: C.3; SheetNumber: 4; SheetTotal: 7; Project: NUCLEO-XXXXRX
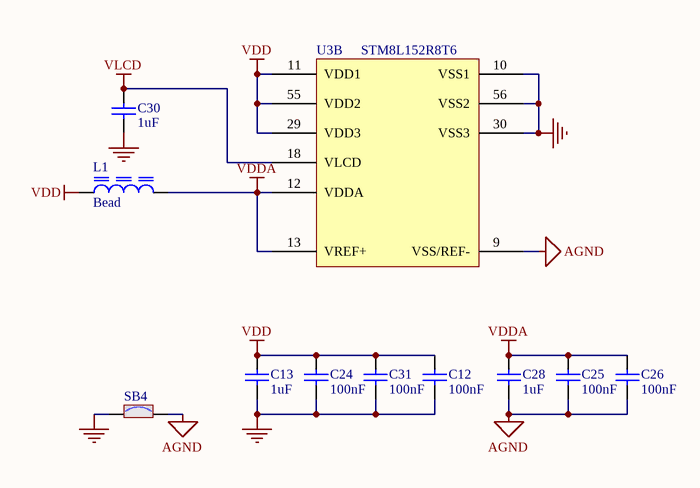
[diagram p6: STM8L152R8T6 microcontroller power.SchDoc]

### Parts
C12  value 100nF  [C0603]  (hidden comment: C)
C13  value 1uF  [C0603]  (hidden comment: C)
C24  value 100nF  [C0603]  (hidden comment: C)
C25  value 100nF  [C0603]  (hidden comment: C)
C26  value 100nF  [C0603]  (hidden comment: C)
C28  value 1uF  [C0603]  (hidden comment: C)
C30  value 1uF  [C0603]  (hidden comment: C)
C31  value 100nF  [C0603]  (hidden comment: C)
L1  value Bead  [L0603]  (hidden comment: L)
SB4  SB_ON  [JP2_SMD]  (value not drawn)
U3  STM8L152R8T6  [QFP50P1000X1000X160-64N]  (part B of 2)

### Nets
AGND: C25.2 C26.2 C28.2 SB4.2 U3.9(VSS/REF-)
GND: C12.2 C13.2 C24.2 C30.2 C31.2 SB4.1 U3.10(VSS1) U3.30(VSS3) U3.56(VSS2)
VDD: C12.1 C13.1 C24.1 C31.1 L1.1 U3.11(VDD1) U3.29(VDD3) U3.55(VDD2)
VDDA: C25.1 C26.1 C28.1 L1.2 U3.12(VDDA) U3.13(VREF+)
VLCD: C30.1 U3.18(VLCD)

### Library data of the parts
C12 C24-C26 C31 = 1004001100110: as C7 on sheet Power
C13 C28 C30 = 1004001100120: as C10 on sheet Power
L1 = 1005005100118: Ferrite Bead,600ohm@100MHz,+/-25%,1000mA,0.2ohm,SMD0603; Manufacturer: TAI-TECH; Manufacturer_Part_Number: HCB1608KF-601T10
SB4 = PN029: as SB19 on sheet Power
U3 = 1002002100257C: as U3 on sheet STM8L152R8T6 microcontroller IOs

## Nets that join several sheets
3V3: Power (JP3.1 SB19.2), ST-LinkV2_SWIM (R2.1 R12.2), Arduino_extension_connectors (5 pins)
5V: Power (9 pins), ST-LinkV2_SWIM (D1.2), Arduino_extension_connectors (CN1.18 CN5.5)
5V_STLINK: ST-LinkV2_SWIM (11 pins), Arduino_extension_connectors (CN9.8)
5V_STLINK_SW: Power (JP2.1), ST-LinkV2_SWIM (C34.2 U7.6 U7.7)
5V_USB_CHG: Power (JP2.7), ST-LinkV2_SWIM (SB1.2)
5V_VIN: Power (C33.2 JP2.3 U5.2 U5.4), ST-LinkV2_SWIM (D3.2), Arduino_extension_connectors (R4.2)
AGND: Arduino_extension_connectors (CN9.32), STM8L152R8T6 microcontroller power (5 pins)
E5V: Power (JP2.5), ST-LinkV2_SWIM (D2.2), Arduino_extension_connectors (CN1.6)
GND: Power (10 pins), ST-LinkV2_SWIM (46 pins), Arduino_extension_connectors (11 pins), STM8L152R8T6 microcontroller IOs (10 pins), STM8L152R8T6 microcontroller power (9 pins)
VDD: Power (JP3.2), Arduino_extension_connectors (CN1.5), STM8L152R8T6 microcontroller IOs (R6.2), STM8L152R8T6 microcontroller power (8 pins)
VDDA: Arduino_extension_connectors (CN8.8 CN9.7), STM8L152R8T6 microcontroller power (6 pins)
VIN: Power (C32.2 U5.3), Arduino_extension_connectors (CN1.24 CN5.8)
VLCD: Arduino_extension_connectors (CN1.33), STM8L152R8T6 microcontroller power (C30.1 U3.18)
PA0: Arduino_extension_connectors (CN1.37), STM8L152R8T6 microcontroller IOs (SB10.1)
PA1: Arduino_extension_connectors (CN1.23), STM8L152R8T6 microcontroller IOs (SB11.1)
PA2: Arduino_extension_connectors (SB8.1), STM8L152R8T6 microcontroller IOs (R20.2 SB7.2 U3.3)
PA3: Arduino_extension_connectors (SB6.1), STM8L152R8T6 microcontroller IOs (R23.1 U3.4)
PA4: Arduino_extension_connectors (CN1.29), STM8L152R8T6 microcontroller IOs (U3.5)
PA5: Arduino_extension_connectors (CN1.31), STM8L152R8T6 microcontroller IOs (U3.6)
PA6: Arduino_extension_connectors (CN1.30 CN4.2), STM8L152R8T6 microcontroller IOs (U3.7)
PA7: Arduino_extension_connectors (CN1.35), STM8L152R8T6 microcontroller IOs (U3.8)
PB0: Arduino_extension_connectors (SB12.1), STM8L152R8T6 microcontroller IOs (U3.31)
PB1: Arduino_extension_connectors (SB14.1), STM8L152R8T6 microcontroller IOs (U3.32)
PB2: Arduino_extension_connectors (CN1.34 CN4.4), STM8L152R8T6 microcontroller IOs (U3.33)
PB3: Arduino_extension_connectors (CN1.32 CN4.3), STM8L152R8T6 microcontroller IOs (U3.34)
PB4: Arduino_extension_connectors (CN8.3 CN9.17), STM8L152R8T6 microcontroller IOs (U3.35)
PB5: Arduino_extension_connectors (CN8.6 CN9.11 SB5.1), STM8L152R8T6 microcontroller IOs (U3.36)
PB6: Arduino_extension_connectors (CN8.4 CN9.15), STM8L152R8T6 microcontroller IOs (U3.37)
PB7: Arduino_extension_connectors (CN8.5 CN9.13), STM8L152R8T6 microcontroller IOs (U3.38)
PC0: Arduino_extension_connectors (CN8.9 CN9.5 SB15.2), STM8L152R8T6 microcontroller IOs (U3.53)
PC1: Arduino_extension_connectors (CN8.10 CN9.3 SB13.2), STM8L152R8T6 microcontroller IOs (U3.54)
PC2: Arduino_extension_connectors (CN7.6 CN9.27), STM8L152R8T6 microcontroller IOs (U3.57)
PC3: Arduino_extension_connectors (CN7.7 CN9.25), STM8L152R8T6 microcontroller IOs (U3.58)
PC4: Arduino_extension_connectors (CN8.2 CN9.19), STM8L152R8T6 microcontroller IOs (U3.59)
PC5: Arduino_extension_connectors (SB17.1), STM8L152R8T6 microcontroller IOs (R14.1 U3.60)
PC6: Arduino_extension_connectors (SB16.1), STM8L152R8T6 microcontroller IOs (R13.1 U3.61)
PC7: Arduino_extension_connectors (CN1.28 CN4.1), STM8L152R8T6 microcontroller IOs (U3.62)
PD0: Arduino_extension_connectors (CN9.26), STM8L152R8T6 microcontroller IOs (U3.25)
PD1: Arduino_extension_connectors (CN7.8 CN9.23), STM8L152R8T6 microcontroller IOs (U3.26)
PD2: Arduino_extension_connectors (CN9.24), STM8L152R8T6 microcontroller IOs (U3.27)
PD3: Arduino_extension_connectors (CN8.1 CN9.21), STM8L152R8T6 microcontroller IOs (U3.28)
PD4: Arduino_extension_connectors (CN9.6), STM8L152R8T6 microcontroller IOs (U3.45)
PD5: Arduino_extension_connectors (CN9.4), STM8L152R8T6 microcontroller IOs (U3.46)
PD6: Arduino_extension_connectors (CN9.2), STM8L152R8T6 microcontroller IOs (U3.47)
PD7: Arduino_extension_connectors (CN9.1), STM8L152R8T6 microcontroller IOs (U3.48)
PE0: Arduino_extension_connectors (CN7.3 CN9.33), STM8L152R8T6 microcontroller IOs (U3.19)
PE1: Arduino_extension_connectors (CN7.4 CN9.31), STM8L152R8T6 microcontroller IOs (U3.20)
PE2: Arduino_extension_connectors (CN7.5 CN9.29), STM8L152R8T6 microcontroller IOs (U3.21)
PE3: Arduino_extension_connectors (CN9.34), STM8L152R8T6 microcontroller IOs (SB2.2)
PE4: Arduino_extension_connectors (CN9.30), STM8L152R8T6 microcontroller IOs (SB3.2)
PE5: Arduino_extension_connectors (CN9.28), STM8L152R8T6 microcontroller IOs (U3.24)
PE6: Arduino_extension_connectors (CN1.13), STM8L152R8T6 microcontroller IOs (U3.63)
PE7: Arduino_extension_connectors (CN1.7), STM8L152R8T6 microcontroller IOs (U3.64)
PF0: Arduino_extension_connectors (CN9.22), STM8L152R8T6 microcontroller IOs (U3.39)
PF1: Arduino_extension_connectors (CN9.18), STM8L152R8T6 microcontroller IOs (U3.40)
PF4: Arduino_extension_connectors (CN9.16), STM8L152R8T6 microcontroller IOs (U3.41)
PF5: Arduino_extension_connectors (CN9.14), STM8L152R8T6 microcontroller IOs (U3.42)
PF6: Arduino_extension_connectors (CN9.12), STM8L152R8T6 microcontroller IOs (U3.43)
PF7: Arduino_extension_connectors (CN9.10), STM8L152R8T6 microcontroller IOs (U3.44)
PG0: Arduino_extension_connectors (CN7.1 CN9.37), STM8L152R8T6 microcontroller IOs (U3.14)
PG1: Arduino_extension_connectors (CN7.2 CN9.35), STM8L152R8T6 microcontroller IOs (U3.15)
PG2: Arduino_extension_connectors (CN9.38), STM8L152R8T6 microcontroller IOs (U3.16)
PG3: Arduino_extension_connectors (CN9.36), STM8L152R8T6 microcontroller IOs (U3.17)
PG4: Arduino_extension_connectors (CN1.1), STM8L152R8T6 microcontroller IOs (SB18.1 U3.49)
PG5: Arduino_extension_connectors (CN1.3), STM8L152R8T6 microcontroller IOs (U3.50)
PG6: Arduino_extension_connectors (CN1.4), STM8L152R8T6 microcontroller IOs (U3.51)
PG7: Arduino_extension_connectors (CN1.2), STM8L152R8T6 microcontroller IOs (U3.52)
T_MCO: ST-LinkV2_SWIM (C21.2 R21.2), STM8L152R8T6 microcontroller IOs (SB7.1)
T_NRST: ST-LinkV2_SWIM (R16.1), Arduino_extension_connectors (CN1.14 CN5.3), STM8L152R8T6 microcontroller IOs (5 pins)
T_SWIM: ST-LinkV2_SWIM (R9.1), STM8L152R8T6 microcontroller IOs (SB10.2 U3.1)
T_VCP_RX: ST-LinkV2_SWIM (SB22.1), STM8L152R8T6 microcontroller IOs (SB2.1 U3.22)
T_VCP_TX: ST-LinkV2_SWIM (SB20.1), STM8L152R8T6 microcontroller IOs (SB3.1 U3.23)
